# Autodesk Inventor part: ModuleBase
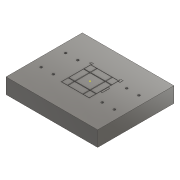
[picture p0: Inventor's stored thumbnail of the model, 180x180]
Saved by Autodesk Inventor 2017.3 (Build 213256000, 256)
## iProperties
Part Number: ModuleBase
Material: ステンレス鋼
Document SubType Name: Modeling
Designer: kyushu-hep
Density: 8 g/cm^3
Appearance: 半つや出し
Mass: 96.9479 g
Surface Area: 172.882 cm^2
Volume: 104.245 cm^3
Author: kyushu-hep
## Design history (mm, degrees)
sketch "スケッチ1"
  geometry: L1 (-60, 50)-(60, 50); L2 (60, 50)-(60, -50); L3 (60, -50)-(-60, -50); L4 (-60, -50)-(-60, 50); 1 further point
  constraints: 8 end point, 2 parallel, 1 horizontal, 1 perpendicular
  dimensions: "d0" = 120 distance of L2.end L3.end; "d1" = 100 distance of L1.end L2.end; "d22" = 50 distance from line of point (0, 0) L3; "d23" = 60 distance from line of L2 point (0, 0)
extrude "押し出し1" new body sketch "スケッチ1" distance "d2" = 20; taper "d3" = 0 deg
sketch "スケッチ4"
  geometry: L1 (17.855, 22.225)-(17.855, 20.225); L2 (17.855, 20.225)-(19.055, 20.225); L3 (19.055, 20.225)-(19.055, 18.225); L4 (19.055, 18.225)-(21.055, 18.225); L5 (21.055, 18.225)-(21.055, 22.225); L6 (21.055, 22.225)-(17.855, 22.225); L7 (21.055, 5)-(21.055, -5); L8 (21.055, -5)-(19.055, -5); L9 (19.055, -5)-(19.055, 5); L10 (19.055, 5)-(21.055, 5); L11 (-60, -50)-(60, -50) reference; L12 (-60, 50)-(-60, -50) reference; L13 (-21.055, 22.225)-(-17.855, 22.225); L14 (-17.855, 22.225)-(-17.855, 20.225); L15 (-17.855, 20.225)-(-21.055, 20.225); L16 (-21.055, 20.225)-(-21.055, 22.225); 1 further point
  constraints: 28 end point, 8 perpendicular, 4 point on line, 2 parallel, 1 collinear, 1 horizontal, 1 vertical
  dimensions: "d12" = 2 distance of L1.start L1.end; "d13" = 1.2 distance of L1.end L2.end; "d14" = 2 distance of L2.end L3.end; "d15" = 2 distance of L3.end L4.end; "d16" = 10 distance of L7.start L7.end; "d24" = 19.055 distance from line of L9 point (0, 0); "d25" = 22.225 distance from line of point (0, 0) L6; "d28" = 17.855 distance from line of point (0, 0) L14
extrude "押し出し4" join sketch "スケッチ4" distance "d29" = 0.3; taper "d30" = 0 deg
sketch "スケッチ6"
  geometry: L1 (20, 20)-(-20, 20); L2 (-20, 20)-(-20, -20); L3 (-20, -20)-(20, -20); L4 (20, -20)-(20, 20); L5 (20, 20)-(-20, -20); L6 (-20, 20)-(20, -20); C1 r 1.5 at (-16, -16); C2 r 1.5 at (-16, 16); C3 r 1.5 at (16, -16); C4 r 1.5 at (16, 16); 1 further point
  constraints: 12 end point, 4 centre point, 2 horizontal, 2 midpoint, 2 parallel, 1 perpendicular, 1 vertical, 6 other
  dimensions: "d41" = 3 diameter of C1; "d42" = 16 horizontal distance of point (0, 0) C1.centre; "d43" = 16 horizontal distance of point (0, 0) C1.centre; "d44" = 40 distance of L3.end L2.end; "d45" = 40 distance of L2.end L1.end; "d48" = 32 distance of C1.centre C2.centre; "d51" = 32 distance of C1.centre C3.centre
sketch "スケッチ7"
  geometry: C1 r 0.5 at (-10, 10); C2 r 0.5 at (10, 10); C3 r 0.5 at (-10, -10); C4 r 0.5 at (10, -10); 1 further point
  constraints: 4 centre point
  dimensions: "d58" = 1 diameter of C1; "d59" = 10 horizontal distance of point (0, 0) C1.centre; "d60" = 10 horizontal distance of point (0, 0) C1.centre; "d61" = 1 diameter of C2; "d62" = 10 horizontal distance of point (0, 0) C2.centre; "d63" = 1 diameter of C3; "d64" = 10 horizontal distance of point (0, 0) C3.centre; "d65" = 1 diameter of C4
extrude "押し出し9" cut sketch "スケッチ7" distance "d66" = 10; taper "d67" = 0 deg
sketch "スケッチ9"
  geometry: L1 (18.5, -19.5)-(-18.5, -19.5); L2 (-18.5, -19.5)-(-18.5, 19.5); L3 (-18.5, 19.5)-(18.5, 19.5); L4 (18.5, 19.5)-(18.5, -19.5); L5 (18.5, -19.5)-(-18.5, 19.5); L6 (-18.5, -19.5)-(18.5, 19.5); L7 (-10.5, 10.5)-(-18, 10.5); L8 (-18, 10.5)-(-18, 19); L9 (-18, 19)-(-10.5, 19); L10 (-10.5, 19)-(-10.5, 10.5); L11 (-10.5, 10.5)-(-18, 19); L12 (-18, 10.5)-(-10.5, 19); L13 (18, 10.5)-(10.5, 10.5); L14 (10.5, 10.5)-(10.5, 19); L15 (10.5, 19)-(18, 19); L16 (18, 19)-(18, 10.5); L17 (-9.5, 19)-(9.5, 19); L18 (9.5, 19)-(9.5, 10.5); L19 (9.5, 10.5)-(-9.5, 10.5); L20 (-9.5, 10.5)-(-9.5, 19); L21 (-18, 9.5)-(-10.5, 9.5); L22 (-10.5, 9.5)-(-10.5, -9.5); L23 (-10.5, -9.5)-(-18, -9.5); L24 (-18, -9.5)-(-18, 9.5); L25 (-18, -10.5)-(-10.5, -10.5); L26 (-10.5, -10.5)-(-10.5, -19); L27 (-10.5, -19)-(-18, -19); L28 (-18, -19)-(-18, -10.5); L29 (-9.5, 9.5)-(9.5, 9.5); L30 (9.5, 9.5)-(9.5, -9.5); L31 (9.5, -9.5)-(-9.5, -9.5); L32 (-9.5, -9.5)-(-9.5, 9.5); L33 (10.5, 9.5)-(18, 9.5); L34 (18, 9.5)-(18, -9.5); L35 (18, -9.5)-(10.5, -9.5); L36 (10.5, -9.5)-(10.5, 9.5); L37 (-9.5, -10.5)-(9.5, -10.5); L38 (9.5, -10.5)-(9.5, -19); L39 (9.5, -19)-(-9.5, -19); L40 (-9.5, -19)-(-9.5, -10.5); L41 (10.5, -10.5)-(18, -10.5); L42 (18, -10.5)-(18, -19); L43 (18, -19)-(10.5, -19); L44 (10.5, -19)-(10.5, -10.5); 2 further points
  constraints: 88 end point, 20 parallel, 19 collinear, 10 horizontal, 10 perpendicular, 4 midpoint, 4 point on line
  dimensions: "d78" = 37 distance of L2.end L3.end; "d79" = 39 distance of L1.end L2.end; "d80" = 7.5 distance of L8.end L9.end; "d81" = 0.5 distance between parallel lines of L3 L9; "d82" = 0.5 distance between parallel lines of L2 L8; "d83" = 8.5 distance of L7.end L8.end; "d88" = 19 distance of L18.end L19.end; "d89" = 8.5 distance of L17.end L18.end; "d90" = 1 distance between parallel lines of L10 L20; "d92" = 19 distance of L21.end L22.end; "d93" = 1 distance between parallel lines of L21 L7; "d94" = 8.5 distance of L25.end L26.end; "d95" = 1 distance between parallel lines of L25 L23; "d96" = 8.5 distance of L13.end L14.end; "d97" = 1 distance between parallel lines of L14 L18
extrude "押し出し11" cut sketch "スケッチ9" distance "d98" = 1; taper "d99" = 0 deg
extrude "押し出し13" cut sketch "スケッチ6" distance "d102" = 10; taper "d103" = 0 deg
sketch "スケッチ10"
  geometry: 1 further point
sketch "スケッチ11"
  geometry: L1 (20, 20)-(-20, 20); L2 (-20, 20)-(-20, -20); L3 (-20, -20)-(20, -20); L4 (20, -20)-(20, 20); L5 (20, 20)-(-20, -20); L6 (-20, 20)-(20, -20); C1 r 1.5 at (-48, -16); C2 r 1.5 at (-48, 16); C3 r 1.5 at (-32, -16); C4 r 1.5 at (-32, 16); C5 r 1.5 at (-16, -16); C6 r 1.5 at (-16, 16); C7 r 1.5 at (0, -16); C8 r 1.5 at (0, 16); C9 r 1.5 at (16, -16); C10 r 1.5 at (16, 16); C11 r 1.5 at (32, -16); C12 r 1.5 at (32, 16); C13 r 1.5 at (48, -16); C14 r 1.5 at (48, 16); 3 further points
  constraints: 14 centre point, 12 end point, 2 horizontal, 2 midpoint, 2 parallel, 1 perpendicular, 1 vertical, 26 other
  dimensions: "d108" = 3 diameter of C1; "d109" = 48 horizontal distance of point (0, 0) C1.centre; "d110" = 16 vertical distance of point (0, 0) C1.centre; "d111" = 40 distance of L3.end L2.end; "d112" = 40 distance of L2.end L1.end; "d113" = 32 distance of C1.centre C2.centre; "d114" = 16 distance of C1.centre C3.centre
extrude "押し出し14" cut sketch "スケッチ11" distance "d115" = 10; taper "d116" = 0 deg
node "ソリッド1"
